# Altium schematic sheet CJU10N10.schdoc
size 127 x 101 mm
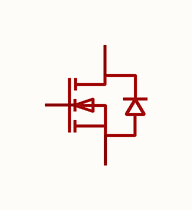
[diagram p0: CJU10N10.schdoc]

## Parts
Q?  cju10n10  [TO-252-3_L6.5-W5.8-P4.58-BR]  (value not drawn)

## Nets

Not connected (* = marked no-connect by the designer): Q? 1(G) 2(D) 3(S)

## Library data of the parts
Q? = cju10n10: 数量:1个N沟道;漏源电压(Vdss):100V;连续漏极电流(Id):9.6A;导通电阻(RDS(on)):140mΩ@10V;耗散功率(Pd):-;阈值电压(Vgs(th)):2.5V;; Manufacturer: CJ(江苏长电/长晶); AddInBom: yes; ModelId: 3eac9db95c5b4fb0ba6d50c62f0c8747; ModelName: TO-252-3_L6.5-W6.1-H2.3-LS10.0-P4.58; ModelTransform: 255.905,390.52442,0,90,0,0,-29.39,0,0; Number: 1个N沟道; Drain to Source Voltage: 100V; Current - Continuous Drain(Id): 9.6A; Gate Threshold Voltage (Vgs(th)): 2.5V; Gate Charge(Qg): 15.5nC@10V; Input Capacitance(Ciss): 690pF; Reverse Transfer Capacitance (Crss@Vds): 90pF; Type: N沟道; Output Capacitance(Coss): 120pF; Vgs: ±20V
